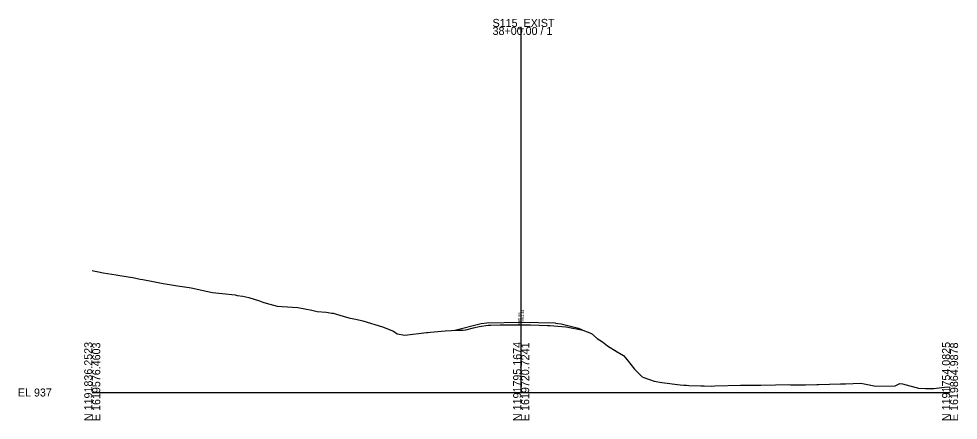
# Model space of a CAD drawing. Extents: x 1620351 to 1620680, y 1192592 to 1195749.
# Drawn here: x 1620351.1 to 1620679.6, y 1194591.8 to 1194732.2 of the extents above; entities that cross this region are included whole.
import ezdxf

# ---------------------------------------------------------------- set-up
doc = ezdxf.new("R2010")
doc.units = 0
for name, color, linetype in [('RD_GPK_XS_Cell', 7, 'Continuous'), ('RD_XS_EarthShd', 7, 'Continuous'), ('RD_XS_ExGround', 7, 'Continuous'), ('RD_XS_Pave', 7, 'Continuous'), ('RD_XS_TieSlope', 7, 'Continuous'), ('RD_XS_TX_Elev_EX', 7, 'Continuous'), ('RD_XS_TX_Elev_PR', 7, 'Continuous')]:
    doc.layers.add(name, color=color, linetype=linetype)

msp = doc.modelspace()

# ---------------------------------------------------------------- linework, layer by layer
at = {"layer": 'RD_GPK_XS_Cell'}
for p, q in [((1620526.76, 1194601.47), (1620526.76, 1194729.36)), ((1620376.76, 1194601.47), (1620526.76, 1194601.47)), ((1620526.76, 1194601.47), (1620676.76, 1194601.47))]:
    msp.add_line(p, q, dxfattribs=at)
at = {"layer": 'RD_XS_EarthShd'}
for p, q in [((1620514.76, 1194625.67), (1620512.76, 1194625.51)), ((1620538.76, 1194625.67), (1620540.76, 1194625.51))]:
    msp.add_line(p, q, dxfattribs=at)
at = {"layer": 'RD_XS_ExGround'}
msp.add_lwpolyline([(1620376.76, 1194644.1), (1620377.16, 1194644.02), (1620379, 1194643.69), (1620380.56, 1194643.37), (1620385.12, 1194642.67), (1620385.7, 1194642.57), (1620389.32, 1194641.94), (1620390.96, 1194641.65), (1620393.54, 1194641.11), (1620394.4, 1194640.95), (1620398.61, 1194640.19), (1620401.6, 1194639.6), (1620403.04, 1194639.35), (1620406.52, 1194638.8), (1620410.62, 1194638.15), (1620411.39, 1194638.05), (1620417.14, 1194636.78), (1620418.84, 1194636.44), (1620422.14, 1194636.06), (1620426.76, 1194635.63), (1620427.44, 1194635.44), (1620429.37, 1194635.12), (1620431.57, 1194634.72), (1620435.24, 1194633.49), (1620436.36, 1194633.06), (1620437.55, 1194632.69), (1620441.47, 1194631.66), (1620443.12, 1194631.58), (1620448.6, 1194631.19), (1620453.58, 1194630.24), (1620455.47, 1194629.83), (1620458.59, 1194629.57), (1620460.58, 1194629.27), (1620460.98, 1194629.19), (1620465.64, 1194627.78), (1620466.96, 1194627.5), (1620468.9, 1194627.07), (1620471.38, 1194626.51), (1620478.24, 1194624.46), (1620482.08, 1194622.93), (1620483.43, 1194621.94), (1620486.05, 1194621.54), (1620493.69, 1194622.41), (1620494.08, 1194622.46), (1620495.06, 1194622.57), (1620500.22, 1194623.05), (1620502.33, 1194623.18), (1620504.34, 1194623.22), (1620506.5, 1194623.26), (1620507.46, 1194623.35), (1620510.13, 1194624.12), (1620512.04, 1194624.51), (1620515.17, 1194624.97), (1620515.75, 1194625.03), (1620516.19, 1194625.04), (1620519.37, 1194625.11), (1620519.88, 1194625.12), (1620521.68, 1194625.14), (1620524.74, 1194625.17), (1620526.76, 1194625.13), (1620527.16, 1194625.12), (1620528.13, 1194625.11), (1620529.12, 1194625.1), (1620530.06, 1194625.11), (1620533.05, 1194625), (1620536, 1194624.92), (1620536.8, 1194624.92), (1620542.34, 1194624.44), (1620543.1, 1194624.37), (1620547.91, 1194623.39), (1620548.37, 1194623.3), (1620551.32, 1194622.05), (1620553.36, 1194620.35), (1620555.21, 1194619.18), (1620557, 1194617.79), (1620560.34, 1194615.73), (1620562.49, 1194614.46), (1620563.81, 1194612.93), (1620566.34, 1194609.61), (1620569.03, 1194606.91), (1620569.65, 1194606.75), (1620573.28, 1194605.47), (1620575.95, 1194605), (1620582.35, 1194604.2), (1620583.6, 1194604.06), (1620584.63, 1194603.98), (1620585.42, 1194603.92), (1620589.58, 1194603.83), (1620590.72, 1194603.82), (1620593.26, 1194603.74), (1620594.46, 1194603.77), (1620603.43, 1194604), (1620604.91, 1194604.04), (1620609.28, 1194604.09), (1620610.56, 1194604.01), (1620615.74, 1194604.11), (1620620.27, 1194604.23), (1620621, 1194604.12), (1620622.37, 1194604.15), (1620626.14, 1194604.2), (1620630.19, 1194604.25), (1620630.75, 1194604.27), (1620638.49, 1194604.46), (1620639.61, 1194604.51), (1620640.17, 1194604.5), (1620645.55, 1194604.71), (1620650.74, 1194603.74), (1620657.61, 1194603.85), (1620659.15, 1194604.6), (1620660.17, 1194604.53), (1620665.71, 1194603), (1620668.16, 1194602.89), (1620671.08, 1194602.91), (1620675.75, 1194603.41), (1620676.76, 1194603.31)], dxfattribs=at)
at = {"layer": 'RD_XS_Pave'}
for p, q in [((1620526.76, 1194625.91), (1620514.76, 1194625.67)), ((1620538.76, 1194625.67), (1620526.76, 1194625.91))]:
    msp.add_line(p, q, dxfattribs=at)
at = {"layer": 'RD_XS_TieSlope'}
for p, q in [((1620512.76, 1194625.51), (1620503.54, 1194623.2)), ((1620540.76, 1194625.51), (1620546.76, 1194624.01)), ((1620546.76, 1194624.01), (1620548.06, 1194623.36))]:
    msp.add_line(p, q, dxfattribs=at)

# ---------------------------------------------------------------- texts
at = {"layer": 'RD_GPK_XS_Cell'}
for s, p in [('S115_EXIST', (1620516.76, 1194729.36)), ('38+00.00 / 1', (1620516.76, 1194726.56)), ('EL 937', (1620350.76, 1194600.07))]:
    msp.add_text(s, height=2.8, dxfattribs=at).set_placement(p)
for s, p in [('N 1191836.2523', (1620376.76, 1194591.47)), ('E 1619576.4603', (1620379.56, 1194591.47)), ('N 1191795.1674', (1620526.76, 1194591.47)), ('E 1619720.7241', (1620529.56, 1194591.47)), ('N 1191754.0825', (1620676.76, 1194591.47)), ('E 1619864.9878', (1620679.56, 1194591.47))]:
    msp.add_text(s, height=2.8, rotation=90, dxfattribs=at).set_placement(p)
at = {"layer": 'RD_XS_TX_Elev_EX'}
msp.add_text('960.66', height=1, rotation=90, dxfattribs=at).set_placement((1620526.66, 1194625.23))
at = {"layer": 'RD_XS_TX_Elev_PR'}
msp.add_text(' 961.44', height=1, rotation=90, dxfattribs=at).set_placement((1620527.76, 1194625.91))

doc.saveas('drawing.dxf')
